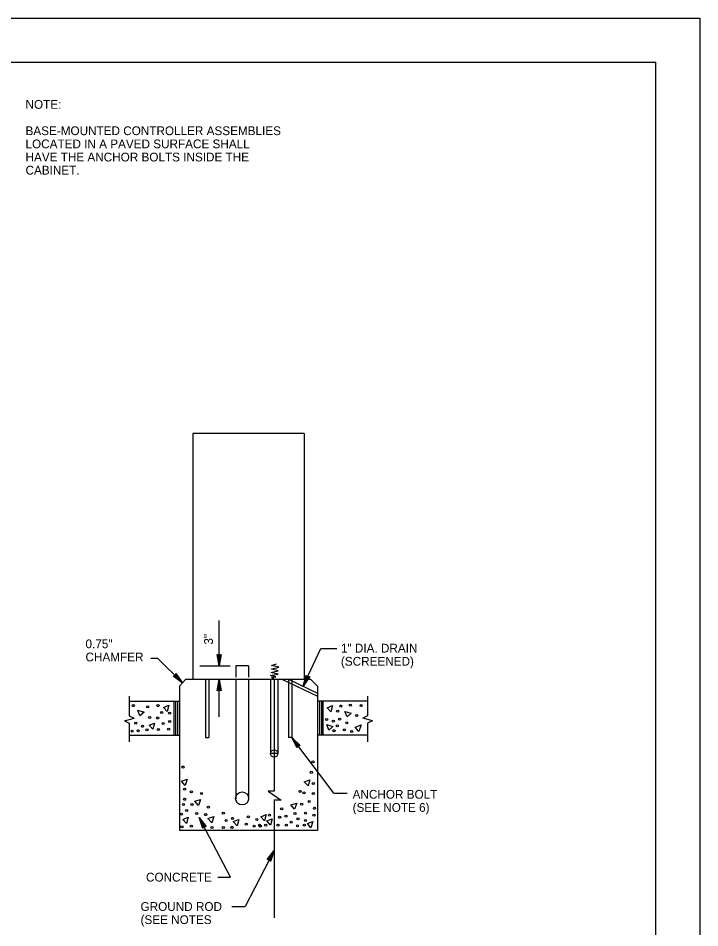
# Model space of a CAD drawing. Extents: x -855 to 49, y 616 to 1210.
# Drawn here: x -247.3 to -14.1, y 899 to 1210.2 of the extents above; entities that cross this region are included whole.
import ezdxf

# ---------------------------------------------------------------- set-up
doc = ezdxf.new("R2010")
doc.units = 0
for name, color, linetype in [('1', 7, 'Continuous'), ('2', 7, 'Continuous'), ('3', 7, 'Continuous'), ('PLT-BNDY', 7, 'Continuous')]:
    doc.layers.add(name, color=color, linetype=linetype)

# ---------------------------------------------------------------- blocks, each defined once
blk = doc.blocks.new('RARROW')
at = {"layer": '3'}
blk.add_lwpolyline([(-2.937125, 0.36875), (-2.82775, 0.156125), (0, 0), (-2.937125, 0.36875), (-3.08775, 0.497625), (0, 0), (-2.8255, -0.13975), (-2.928625, -0.350125), (0, 0), (-3.08775, -0.490625), (-2.928625, -0.350125)], dxfattribs=at)

msp = doc.modelspace()

# ---------------------------------------------------------------- linework, layer by layer
at = {"layer": '1'}
for p in [(-815.14, 1195.17), (-29.14, 631.17)]:
    msp.add_line(p, (-29.14, 1195.17), dxfattribs=at)
at = {"layer": '2'}
for p, q in [((-187.55, 1068.05), (-187.55, 983.92)), ((-149.55, 1068.05), (-187.55, 1068.05)), ((-149.55, 1068.05), (-149.55, 983.92)), ((-178.57, 988.67), (-178.57, 1004.15)), ((-149.8, 981.67), (-143.8, 994.55)), ((-143.8, 994.55), (-138.3, 994.55)), ((-199.55, 991.17), (-201.92, 991.17)), ((-191.17, 982.8), (-199.55, 991.17)), ((-185.19, 988.67), (-174.82, 988.67)), ((-168.55, 988.67), (-172.92, 988.67)), ((-172.92, 988.67), (-172.92, 984.8)), ((-168.55, 988.67), (-168.55, 984.8)), ((-190.05, 983.92), (-192.17, 981.67)), ((-147.17, 983.92), (-190.05, 983.92)), ((-183.3, 983.92), (-183.3, 964.05)), ((-182.17, 983.92), (-182.17, 964.05)), ((-178.57, 971.17), (-178.57, 983.92)), ((-172.92, 983.92), (-172.92, 943.17)), ((-168.55, 983.92), (-168.55, 943.17)), ((-161.02, 983.92), (-161.02, 958.67)), ((-159.77, 983.92), (-159.77, 945.73)), ((-158.52, 983.92), (-158.52, 958.67)), ((-156.92, 983.92), (-144.92, 978.3)), ((-154.92, 983.92), (-154.92, 964.05)), ((-154.67, 983.92), (-144.92, 979.3)), ((-153.67, 983.92), (-153.67, 964.05)), ((-147.17, 983.92), (-144.92, 981.67)), ((-192.17, 981.67), (-192.17, 932.3)), ((-144.92, 981.67), (-144.92, 932.3)), ((-209.42, 978.3), (-209.42, 971.55)), ((-127.8, 978.3), (-127.8, 971.55)), ((-209.42, 976.55), (-192.17, 976.55)), ((-194.05, 976.55), (-194.05, 964.92)), ((-193.55, 976.55), (-193.55, 964.92)), ((-192.8, 976.55), (-192.8, 964.92)), ((-127.8, 976.55), (-144.92, 976.55)), ((-144.3, 976.55), (-144.3, 964.92)), ((-143.55, 976.55), (-143.55, 964.92)), ((-143.17, 976.55), (-143.17, 964.92)), ((-209.42, 971.55), (-207.67, 970.67)), ((-127.8, 971.55), (-129.42, 970.67)), ((-210.92, 969.8), (-207.67, 970.67)), ((-210.92, 969.8), (-209.42, 969.05)), ((-209.42, 969.05), (-209.42, 962.67)), ((-126.17, 969.8), (-129.42, 970.67)), ((-126.17, 969.8), (-127.8, 969.05)), ((-127.8, 969.05), (-127.8, 962.67)), ((-209.42, 964.92), (-192.17, 964.92)), ((-127.8, 964.92), (-144.92, 964.92)), ((-183.3, 964.05), (-182.17, 964.05)), ((-153.67, 964.05), (-154.92, 964.05)), ((-139.3, 945.05), (-153.67, 964.05)), ((-158.52, 958.67), (-161.02, 958.67)), ((-139.3, 945.05), (-134.8, 945.05)), ((-159.77, 942.66), (-159.77, 902.37)), ((-174.74, 916.31), (-185.41, 936.73)), ((-144.92, 932.3), (-192.17, 932.3)), ((-159.77, 925.49), (-169.72, 906.27)), ((-179.07, 916.31), (-174.74, 916.31)), ((-174.25, 906.27), (-169.72, 906.27))]:
    msp.add_line(p, q, dxfattribs=at)
for points in [[(-159.77, 983.92), (-160.66, 984.72), (-159.21, 984.83), (-161.08, 985.35), (-158.38, 985.76), (-160.87, 986.39), (-158.38, 986.91), (-160.66, 987.53), (-158.17, 988.15), (-160.66, 988.78), (-159, 989.3)], [(-197.67, 974.42), (-195.8, 975.17), (-196.42, 973.05), (-197.67, 974.42)], [(-141.67, 974.3), (-139.8, 975.05), (-140.42, 972.92), (-141.67, 974.3)], [(-205.67, 971.55), (-206.42, 973.42), (-204.3, 972.8), (-205.67, 971.55)], [(-134.8, 971.17), (-135.55, 973.05), (-133.42, 972.42), (-134.8, 971.17)], [(-202.55, 968.3), (-200.67, 969.05), (-201.3, 966.92), (-202.55, 968.3)], [(-141.05, 966.67), (-141.8, 968.55), (-139.67, 967.92), (-141.05, 966.67)], [(-132.05, 967.67), (-130.05, 968.42), (-130.8, 966.17), (-132.05, 967.67)], [(-191.42, 949.17), (-189.55, 949.8), (-190.17, 947.67), (-191.42, 949.17)], [(-149.55, 948.92), (-147.55, 949.67), (-148.17, 947.55), (-149.55, 948.92)], [(-186.92, 942.3), (-184.92, 942.92), (-185.67, 940.8), (-186.92, 942.3)], [(-159.78, 945.73), (-161.79, 945.73), (-157.32, 942.67), (-159.78, 942.66)], [(-154.05, 941.05), (-152.05, 941.67), (-152.8, 939.55), (-154.05, 941.05)], [(-191.05, 936.05), (-189.17, 936.8), (-189.8, 934.67), (-191.05, 936.05)], [(-182.42, 936.42), (-180.42, 937.05), (-181.05, 934.92), (-182.42, 936.42)], [(-164.34, 936.99), (-162.46, 937.74), (-163.09, 935.61), (-164.34, 936.99)], [(-173.8, 935.42), (-171.8, 936.05), (-172.42, 933.92), (-173.8, 935.42)], [(-162.3, 935.55), (-160.42, 936.3), (-161.05, 934.17), (-162.3, 935.55)], [(-148.42, 934.67), (-146.55, 935.42), (-147.17, 933.17), (-148.42, 934.67)]]:
    msp.add_lwpolyline(points, dxfattribs=at)
for centre, radius in [((-159.77, 958.65), 1.25), ((-170.73, 943.25), 2.22)]:
    msp.add_circle(centre, radius, dxfattribs=at)
for centre in [(-207.93, 975), (-203.03, 974.6), (-199.5, 975), (-136.95, 974.87), (-133.68, 975.14), (-130.01, 975), (-202.35, 970.92), (-199.63, 970.79), (-198.27, 972.69), (-195.55, 972.42), (-138.04, 973.1), (-131.51, 971.6), (-207.11, 969.02), (-204.8, 967.93), (-197.73, 968.88), (-195.55, 969.56), (-141.84, 970.24), (-139.53, 969.7), (-138.17, 968.07), (-137.36, 970.38), (-134.91, 969.16), (-208.34, 966.3), (-206.3, 966.44), (-203.3, 966.71), (-199.36, 966.85), (-195.83, 966.98), (-139.26, 966.44), (-135.72, 966.71), (-133.28, 966.17), (-146.52, 955.81), (-190.97, 954), (-147.06, 952.19), (-190.43, 946.4), (-150.86, 945.68), (-146.34, 948.39), (-190.43, 942.96), (-188.07, 945.5), (-184.64, 944.95), (-149.6, 945.14), (-146.34, 944.95), (-190.79, 941.15), (-187.89, 941.15), (-182.29, 940.25), (-157.19, 939.71), (-150.32, 941.34), (-147.79, 942.24), (-145.98, 939.89), (-191.51, 937.9), (-189.7, 939.16), (-186.27, 938.08), (-183.19, 937.72), (-177.19, 938.26), (-174.02, 936.45), (-168.59, 936.99), (-161.36, 937.54), (-157.92, 936.81), (-155.75, 937.17), (-152.67, 938.08), (-151.59, 936.27), (-149.05, 938.26), (-146.16, 937.54), (-191.33, 933.56), (-188.07, 933.74), (-181.02, 933.28), (-177.19, 933.28), (-176.19, 935.73), (-174.2, 933.37), (-169.32, 934.46), (-166.6, 933.74), (-165.7, 936.09), (-164.79, 934.1), (-164.46, 933.74), (-162.65, 934.1), (-158.46, 934.1), (-155.57, 934.1), (-153.94, 935.18), (-151.77, 933.92), (-149.41, 934.1), (-149.05, 935.73)]:
    msp.add_ellipse(centre, major_axis=(-0.383, 0), ratio=0.9, dxfattribs=at)
at = {"layer": 'PLT-BNDY'}
msp.add_lwpolyline([(-855.14, 1210.17), (-14.14, 1210.17), (-14.14, 616.17), (-855.14, 616.17)], close=True, dxfattribs=at)

# ---------------------------------------------------------------- block references
at = {"layer": '2'}
for p, xscale, yscale, rotation in [((-178.57, 988.67), 1.2574347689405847, 1.3092961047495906, -90.00000000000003), ((-191.17, 982.8), 1.2574347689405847, 1.3092961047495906, -45.17344630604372), ((-178.57, 983.92), 1.2574347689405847, 1.3092961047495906, 89.99999999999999), ((-149.8, 981.67), 1.2574347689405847, 1.3092961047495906, -114.29753278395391), ((-153.67, 964.05), 1.2574347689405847, 1.3092961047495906, 127.0148034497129), ((-185.41, 936.73), 1.2574347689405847, 1.3092961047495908, 118.07030884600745), ((-159.77, 925.49), 1.257434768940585, 1.3092961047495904, 62.89336667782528)]:
    msp.add_blockref('RARROW', p, dxfattribs=dict(at, xscale=xscale, yscale=yscale, rotation=rotation))

# ---------------------------------------------------------------- texts
for s, p in [('NOTE:', (-244.83, 1179.17)), ('BASE-MOUNTED CONTROLLER ASSEMBLIES', (-244.83, 1170.17)), ('LOCATED IN A PAVED SURFACE SHALL', (-244.83, 1165.67)), ('HAVE THE ANCHOR BOLTS INSIDE THE', (-244.83, 1161.17)), ('CABINET.', (-244.83, 1156.67)), ('0.75"', (-224.31, 994.65)), ('1" DIA. DRAIN', (-136.92, 993.17)), ('CHAMFER', (-224.31, 990.15)), ('(SCREENED)', (-136.92, 988.67)), ('ANCHOR BOLT', (-132.92, 943.17)), ('(SEE NOTE 6)', (-132.92, 938.67)), ('CONCRETE', (-203.61, 914.84)), ('GROUND ROD', (-205.48, 904.79)), ('(SEE NOTES', (-205.48, 900.29))]:
    msp.add_text(s, height=3, dxfattribs=at).set_placement(p)
msp.add_text('3" ', height=3, rotation=90, dxfattribs=at).set_placement((-180.72, 995.88))

doc.saveas('drawing.dxf')
